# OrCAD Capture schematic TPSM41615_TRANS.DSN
size D; title: TPSM41615 4-V to 16-V Input, 15-A DC/DC power module with; rev: 1.0; note: Datasheet: SLVSEW0     EVM: SLVUB16; note: current sharing
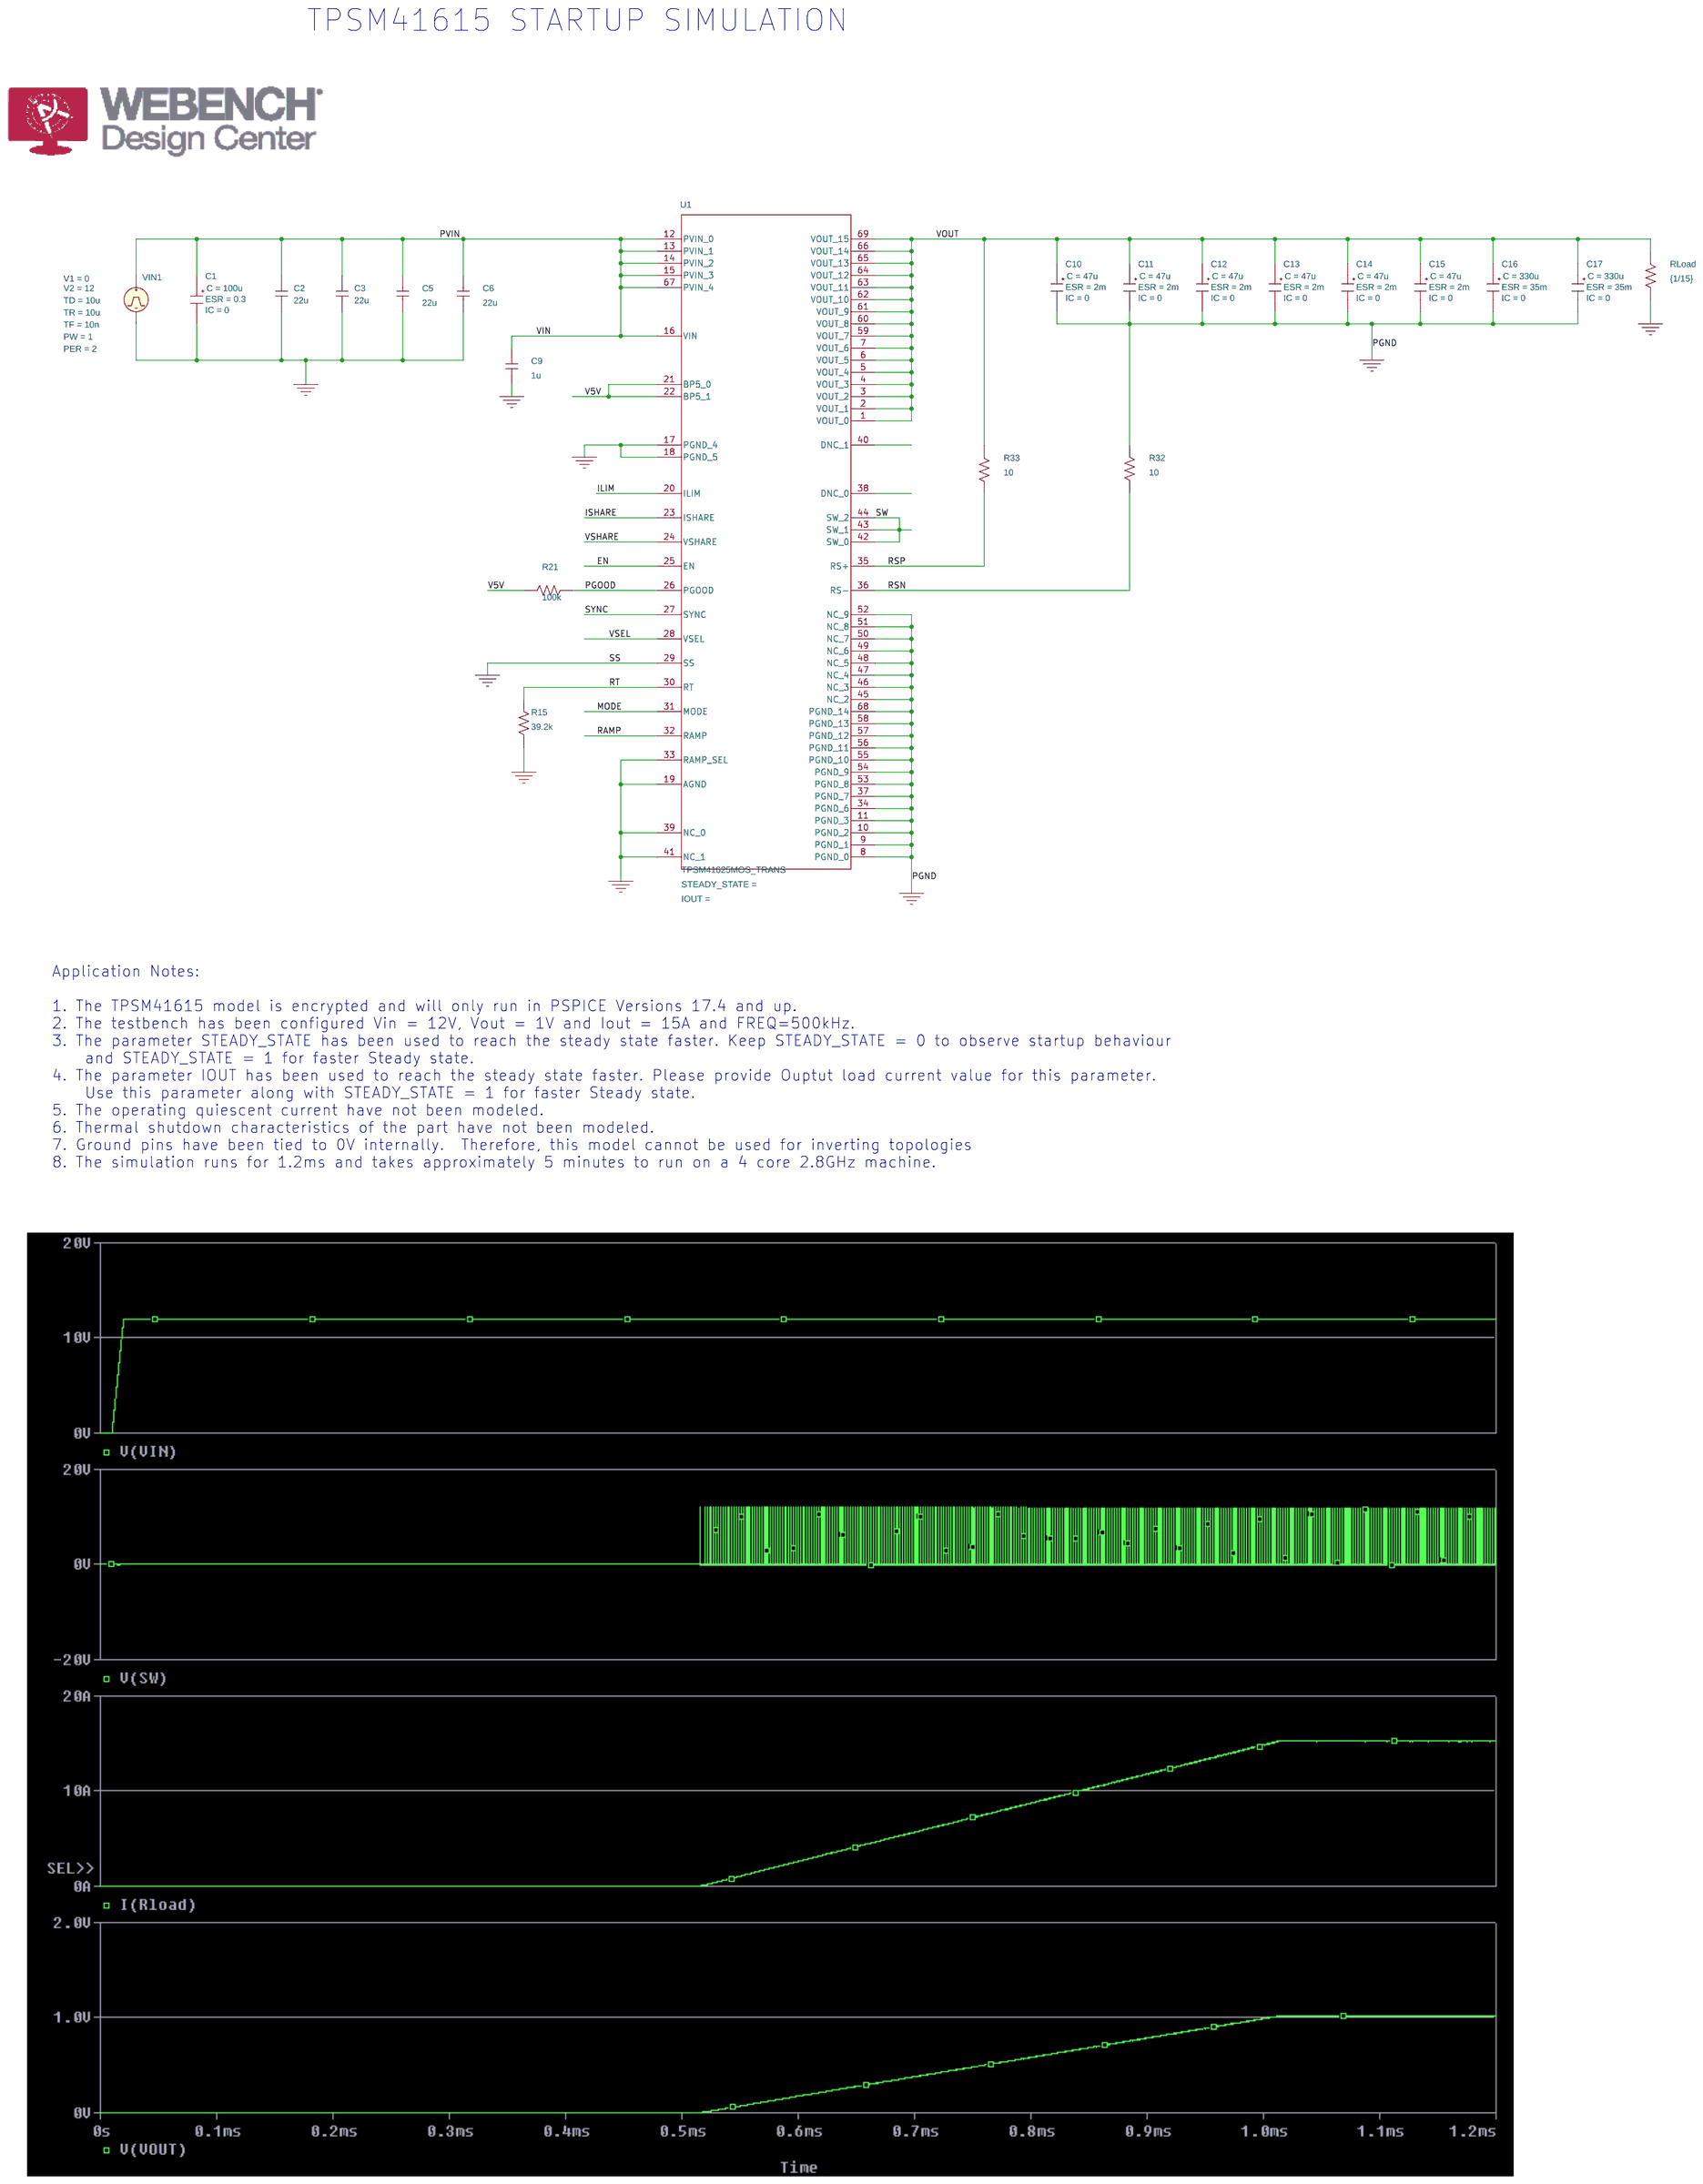
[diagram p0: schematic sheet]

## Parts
C1  CESR
C2  22u  [RAD/CK05]
C3  22u  [RAD/CK05]
C5  22u  [RAD/CK05]
C6  22u  [RAD/CK05]
C9  1u  [RAD/CK05]
C10  CESR
C11  CESR
C12  CESR
C13  CESR
C14  CESR
C15  CESR
C16  CESR
C17  CESR
R15  39.2k  [AX/RC05]
R21  100k  [AX/RC05]
R32  10  [AX/RC05]
R33  10  [AX/RC05]
RLoad  {1/15}  [AX/RC05]
U1  TPSM41625MOS_TRANS  [MOS0069A]
VIN1  VPULSE

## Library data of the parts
C1 = CESR_0: C: 100u; ESR: 0.3; IC: 0; PSpiceTemplate: X^@REFDES %IN %OUT @MODEL PARAMS:  ?C|C=@C||C=100u|  ?ESR|ESR=@ESR||ESR=0.01| ?X|X=@X||X=2|  ?IC|IC=@IC||IC=2|; X: 1
C2 C3 C5 C6 C9 = C
C10-C15 = CESR_0: C: 47u; ESR: 2m; IC: 0; PSpiceTemplate: X^@REFDES %IN %OUT @MODEL PARAMS:  ?C|C=@C||C=100u|  ?ESR|ESR=@ESR||ESR=0.01| ?X|X=@X||X=2|  ?IC|IC=@IC||IC=2|; X: 1
C16 C17 = CESR_0: C: 330u; ESR: 35m; IC: 0; PSpiceTemplate: X^@REFDES %IN %OUT @MODEL PARAMS:  ?C|C=@C||C=100u|  ?ESR|ESR=@ESR||ESR=0.01| ?X|X=@X||X=2|  ?IC|IC=@IC||IC=2|; X: 1
R15 R21 R32 R33 RLoad = R
U1 = TPSM41615MOS_TRANS
VIN1 = VPULSE: PER: 2; PW: 1; TD: 10u; TF: 10n; TR: 10u; V1: 0; V2: 12

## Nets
PVIN: C1.1(IN) C2.2 C3.2 C5.2 C6.2 C9.2 U1.12(PVIN_0) U1.13(PVIN_1) U1.14(PVIN_2) U1.15(PVIN_3) U1.16(VIN) U1.67(PVIN_4) VIN1.1(+)
V5V: R21.1 U1.21(BP5_0) U1.22(BP5_1)
0: C1.2(OUT) C2.1 C3.1 C5.1 C6.1 C9.1 C10.2(OUT) C11.2(OUT) C12.2(OUT) C13.2(OUT) C14.2(OUT) C15.2(OUT) C16.2(OUT) C17.2(OUT) R15.1 R32.2 RLoad.2 U1.8(PGND_0) U1.9(PGND_1) U1.10(PGND_2) U1.11(PGND_3) U1.17(PGND_4) U1.18(PGND_5) U1.19(AGND) U1.29(SS) U1.33(RAMP_SEL) U1.34(PGND_6) U1.37(PGND_7) U1.39(NC_0) U1.41(NC_1) U1.45(NC_2) U1.46(NC_3) U1.47(NC_4) U1.48(NC_5) U1.49(NC_6) U1.50(NC_7) U1.51(NC_8) U1.52(NC_9) U1.53(PGND_8) U1.54(PGND_9) U1.55(PGND_10) U1.56(PGND_11) U1.57(PGND_12) U1.58(PGND_13) U1.68(PGND_14) VIN1.2(-)
EN: U1.25(EN)
ILIM: U1.20(ILIM)
ISHARE: U1.23(ISHARE)
MODE: U1.31(MODE)
PGOOD: R21.2 U1.26(PGOOD)
RAMP: U1.32(RAMP)
RSN: R32.1 U1.36(RS-)
RSP: R33.2 U1.35(RS+)
RT: R15.2 U1.30(RT)
SW: U1.42(SW_0) U1.43(SW_1) U1.44(SW_2)
SYNC: U1.27(SYNC)
VOUT: C10.1(IN) C11.1(IN) C12.1(IN) C13.1(IN) C14.1(IN) C15.1(IN) C16.1(IN) C17.1(IN) R33.1 RLoad.1 U1.1(VOUT_0) U1.2(VOUT_1) U1.3(VOUT_2) U1.4(VOUT_3) U1.5(VOUT_4) U1.6(VOUT_5) U1.7(VOUT_6) U1.59(VOUT_7) U1.60(VOUT_8) U1.61(VOUT_9) U1.62(VOUT_10) U1.63(VOUT_11) U1.64(VOUT_12) U1.65(VOUT_13) U1.66(VOUT_14) U1.69(VOUT_15)
VSEL: U1.28(VSEL)
VSHARE: U1.24(VSHARE)

Not connected (* = marked no-connect by the designer): U1 38(DNC_0) 40(DNC_1)

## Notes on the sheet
- TPSM41615 STARTUP SIMULATION
- Application Notes:
  1. The TPSM41615 model is encrypted and will only run in PSPICE Versions 17.4 and up.
  2. The testbench has been configured Vin = 12V, Vout = 1V and Iout = 15A and FREQ=500kHz.
  3. The parameter STEADY_STATE has been used to reach the steady state faster. Keep STEADY_STATE = 0 to observe startup behaviour
      and STEADY_STATE = 1 for faster Steady state.
  4. The parameter IOUT has been used to reach the steady state faster. Please provide Ouptut load current value for this parameter.
      Use this parameter along with STEADY_STATE = 1 for faster Steady state.
  5. The operating quiescent current have not been modeled.
  6. Thermal shutdown characteristics of the part have not been modeled.
  7. Ground pins have been tied to 0V internally.  Therefore, this model cannot be used for inverting topologies
  8. The simulation runs for 1.2ms and takes approximately 5 minutes to run on a 4 core 2.8GHz machine.
